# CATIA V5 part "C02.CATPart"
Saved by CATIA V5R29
Part number: C02
Source: Unknown
Bounding box of the stored display mesh (mm): x -32.98 to 32.98, y -100 to 300, z -33 to 33
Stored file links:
  C:\가치같이\SmartFactory_BoxErectorConveyor\Boxing(under)\C02.CATPart
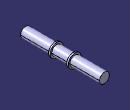
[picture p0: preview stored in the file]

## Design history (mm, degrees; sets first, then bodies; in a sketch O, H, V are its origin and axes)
Body1 (main body)
  Solid1 "PartBody": solid without history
